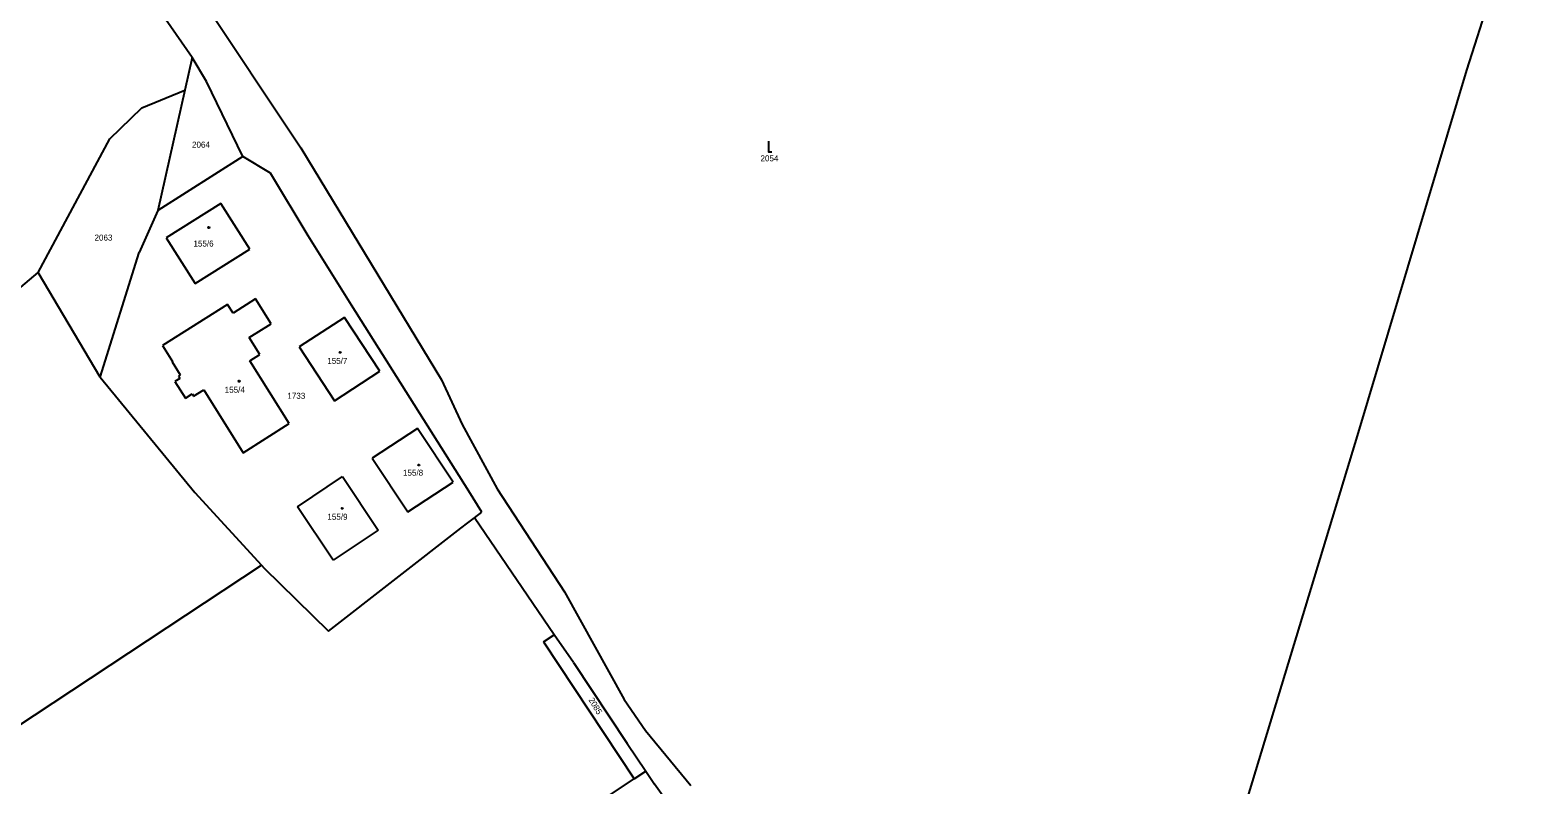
# Model space of a CAD drawing. Extents: x -802857 to -799647, y -1020285 to -1015884.
# Drawn here: x -801184.5 to -800758.7, y -1018304.2 to -1018091.1 of the extents above; entities that cross this region are included whole.
import ezdxf

# ---------------------------------------------------------------- set-up
doc = ezdxf.new("R2010")
doc.units = 0
for name, color, linetype in [('Default', 7, 'Continuous'), ('KN_HRANICE', 7, 'Continuous'), ('KN_KULTURY', 7, 'Continuous'), ('KN_PARCELY', 7, 'Continuous')]:
    doc.layers.add(name, color=color, linetype=linetype)

# ---------------------------------------------------------------- blocks, each defined once
blk = doc.blocks.new('302')
at = {"layer": 'Default'}
blk.add_lwpolyline([(0, 3), (0, 0), (1, 0)], dxfattribs=at)
blk = doc.blocks.new('402')
at = {"layer": 'Default'}
blk.add_lwpolyline([(0.09, 0.15), (0.18, 0), (0.09, -0.15), (-0.09, -0.15), (-0.18, 0), (-0.09, 0.15), (0.09, 0.15)], dxfattribs=at)

msp = doc.modelspace()

# ---------------------------------------------------------------- linework, layer by layer
at = {"layer": 'KN_HRANICE'}
for p, q in [((-800758.73, -1018039.33), (-800778.88, -1018102.34)), ((-801138.76, -1018098.76), (-801154.61, -1018075.98)), ((-801137.52, -1018080.08), (-801108.06, -1018124.29)), ((-801138.76, -1018098.76), (-801140.86, -1018108.06)), ((-801134.75, -1018105.58), (-801138.76, -1018098.76)), ((-800778.88, -1018102.34), (-800809.45, -1018204.72)), ((-801152.98, -1018112.97), (-801140.86, -1018108.06)), ((-801140.86, -1018108.06), (-801148.52, -1018142.01)), ((-801124.44, -1018126.77), (-801134.75, -1018105.58)), ((-801162.02, -1018121.8), (-801152.98, -1018112.97)), ((-801182.26, -1018159.49), (-801162.02, -1018121.8)), ((-801124.44, -1018126.77), (-801148.52, -1018142.01)), ((-801116.68, -1018131.46), (-801124.44, -1018126.77)), ((-801108.06, -1018124.29), (-801068.32, -1018189.86)), ((-801105.99, -1018149.19), (-801116.68, -1018131.46)), ((-801148.52, -1018142.01), (-801153.77, -1018153.86)), ((-801130.69, -1018140.03), (-801146.08, -1018149.73)), ((-801122.54, -1018152.95), (-801130.69, -1018140.03)), ((-801146.08, -1018149.73), (-801137.95, -1018162.61)), ((-801093.81, -1018168.72), (-801105.99, -1018149.19)), ((-801164.76, -1018189.03), (-801153.77, -1018153.86)), ((-801137.95, -1018162.61), (-801122.54, -1018152.95)), ((-801188.42, -1018164.67), (-801182.26, -1018159.49)), ((-801164.76, -1018189.03), (-801182.26, -1018159.49)), ((-801128.77, -1018168.52), (-801147.14, -1018180.09)), ((-801127.24, -1018170.99), (-801128.77, -1018168.52)), ((-801120.9, -1018166.97), (-801127.24, -1018170.99)), ((-801116.5, -1018173.97), (-801120.9, -1018166.97)), ((-801060.67, -1018221.27), (-801093.81, -1018168.72)), ((-801095.74, -1018172.19), (-801108.54, -1018180.52)), ((-801085.8, -1018187.38), (-801095.74, -1018172.19)), ((-801122.69, -1018177.89), (-801116.5, -1018173.97)), ((-801119.71, -1018182.63), (-801122.69, -1018177.89)), ((-801147.14, -1018180.09), (-801144.34, -1018184.67)), ((-801108.54, -1018180.52), (-801098.6, -1018195.74)), ((-801144.34, -1018184.67), (-801144.47, -1018184.75)), ((-801144.47, -1018184.75), (-801142.15, -1018188.46)), ((-801122.54, -1018184.45), (-801119.71, -1018182.63)), ((-801111.39, -1018202.2), (-801122.54, -1018184.45)), ((-801164.76, -1018189.03), (-801137.99, -1018221.64)), ((-801142.29, -1018189.44), (-801143.66, -1018190.3)), ((-801143.66, -1018190.3), (-801140.71, -1018194.98)), ((-801142.15, -1018188.46), (-801142.64, -1018188.78)), ((-801142.64, -1018188.78), (-801142.29, -1018189.44)), ((-801098.6, -1018195.74), (-801085.8, -1018187.38)), ((-801068.32, -1018189.86), (-801062.5, -1018202.43)), ((-801140.71, -1018194.98), (-801138.81, -1018193.8)), ((-801138.81, -1018193.8), (-801138.41, -1018194.44)), ((-801138.41, -1018194.44), (-801135.51, -1018192.63)), ((-801135.51, -1018192.63), (-801124.34, -1018210.42)), ((-801124.34, -1018210.42), (-801111.39, -1018202.2)), ((-801062.5, -1018202.43), (-801052.63, -1018220.57)), ((-801075.13, -1018203.55), (-801087.93, -1018211.91)), ((-801065.07, -1018218.75), (-801075.13, -1018203.55)), ((-800809.45, -1018204.72), (-800858.35, -1018365.54)), ((-801087.93, -1018211.91), (-801077.89, -1018227.11)), ((-801109.06, -1018225.65), (-801096.34, -1018217.16)), ((-801096.34, -1018217.16), (-801086.27, -1018232.32)), ((-801077.89, -1018227.11), (-801065.07, -1018218.75)), ((-801137.99, -1018221.64), (-801119.22, -1018242.16)), ((-801056.96, -1018227.19), (-801060.67, -1018221.27)), ((-801052.63, -1018220.57), (-801033.58, -1018249.7)), ((-801098.98, -1018240.8), (-801109.06, -1018225.65)), ((-801060.89, -1018230.19), (-801059.07, -1018228.8)), ((-801059.07, -1018228.8), (-801056.96, -1018227.19)), ((-801036.5, -1018261.82), (-801059.07, -1018228.8)), ((-801100.25, -1018260.77), (-801062.87, -1018231.7)), ((-801086.27, -1018232.32), (-801098.98, -1018240.8)), ((-801062.87, -1018231.7), (-801060.89, -1018230.19)), ((-801264.84, -1018338.35), (-801119.22, -1018242.16)), ((-801119.22, -1018242.16), (-801118.41, -1018243.04)), ((-801118.41, -1018243.04), (-801100.25, -1018260.77)), ((-801033.58, -1018249.7), (-801016.73, -1018280.08)), ((-801039.54, -1018263.83), (-801036.5, -1018261.82)), ((-801031.12, -1018269.69), (-801036.5, -1018261.82)), ((-801039.54, -1018263.83), (-801013.92, -1018302.5)), ((-801031.12, -1018269.69), (-801015.96, -1018292.57)), ((-801016.73, -1018280.08), (-801010.75, -1018288.86)), ((-801015.96, -1018292.57), (-801010.68, -1018300.36)), ((-801010.75, -1018288.86), (-800997.94, -1018304.44)), ((-801013.92, -1018302.5), (-801010.68, -1018300.36)), ((-801010.68, -1018300.36), (-801008.23, -1018303.98)), ((-801158.11, -1018397.76), (-801013.92, -1018302.5)), ((-800999.13, -1018316.71), (-801008.23, -1018303.98))]:
    msp.add_line(p, q, dxfattribs=at)

# ---------------------------------------------------------------- block references
at = {"layer": 'KN_KULTURY'}
for name, p in [('302', (-800976.05, -1018125.42)), ('402', (-801134.06, -1018146.8)), ('402', (-801096.99, -1018182.06)), ('402', (-801125.5, -1018190.21)), ('402', (-801074.78, -1018213.86)), ('402', (-801096.38, -1018226.09))]:
    msp.add_blockref(name, p, dxfattribs=at)

# ---------------------------------------------------------------- texts
at = {"layer": 'KN_PARCELY'}
for s, p in [('2064', (-801138.83, -1018124.26)), ('2054', (-800978.27, -1018128.12)), ('2063', (-801166.36, -1018150.51)), ('155/6', (-801138.42, -1018152.19)), ('155/7', (-801100.63, -1018185.32)), ('155/4', (-801129.59, -1018193.48)), ('1733', (-801111.89, -1018195.19)), ('155/8', (-801079.24, -1018216.91)), ('155/9', (-801100.59, -1018229.35))]:
    msp.add_text(s, height=1.7, dxfattribs=at).set_placement(p)
msp.add_text('2085', height=1.7, rotation=300.574, dxfattribs=at).set_placement((-801026.91, -1018280.19))

doc.saveas('drawing.dxf')
